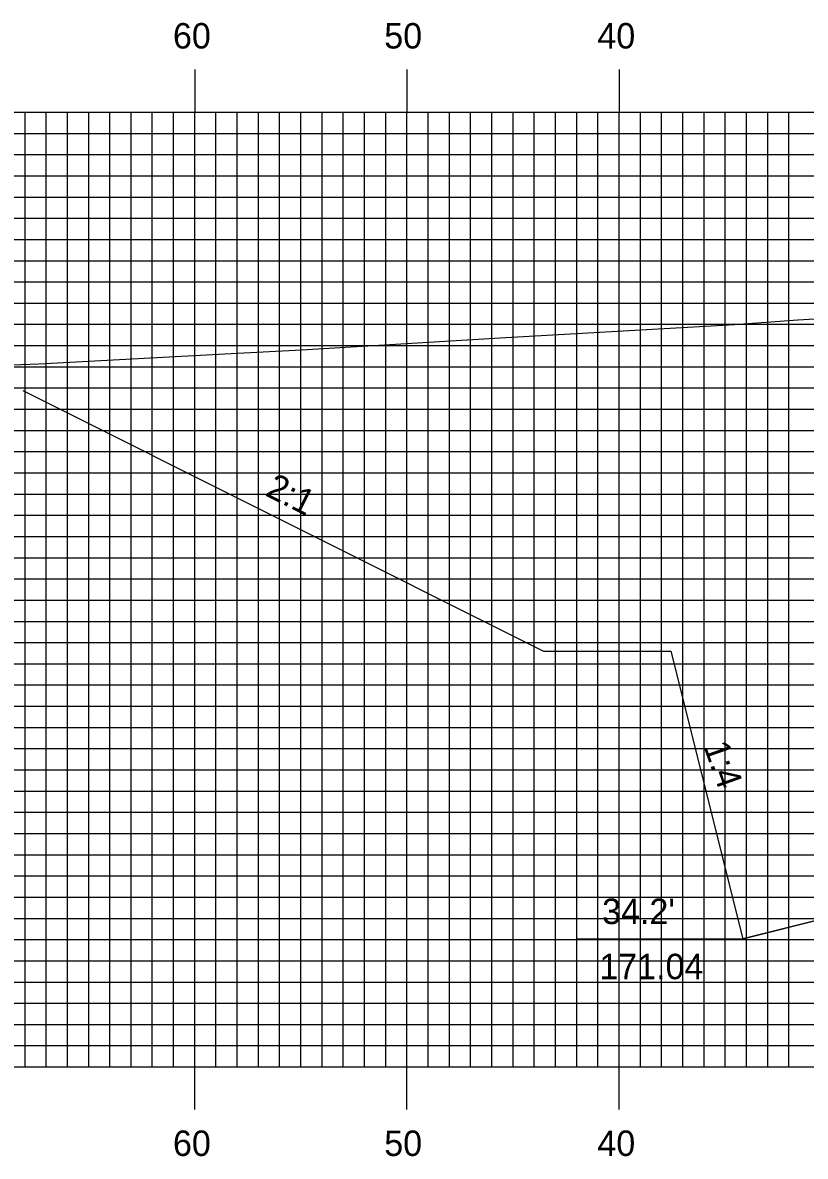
# Model space of a CAD drawing. Extents: x 1795240 to 1795583, y 442591 to 442811.
# Drawn here: x 1795337.3 to 1795374.1, y 442679.4 to 442732.9 of the extents above; entities that cross this region are included whole.
import ezdxf

# ---------------------------------------------------------------- set-up
doc = ezdxf.new("R2010")
doc.units = 0
for name, color, linetype in [('ANNOTATION', 7, 'Continuous'), ('D_Roadway_Centerline', 7, 'Continuous'), ('D_Roadway_SlopeLines', 7, 'Continuous'), ('H_V ANNOTATION', 7, 'Continuous'), ('MAJOR', 7, 'Continuous'), ('MINOR', 7, 'Continuous'), ('PDRAIN', 7, 'Continuous'), ('S_Roadway_Centerline', 7, 'Continuous')]:
    doc.layers.add(name, color=color, linetype=linetype)

msp = doc.modelspace()

# ---------------------------------------------------------------- linework, layer by layer
at = {"layer": 'D_Roadway_Centerline'}
msp.add_lwpolyline([(1795337.256, 442715.538), (1795361.802, 442703.265), (1795367.802, 442703.265), (1795371.192, 442689.704), (1795375.192, 442690.704), (1795385.366, 442693.248), (1795393.366, 442693.568), (1795405.366, 442693.328), (1795417.366, 442693.088), (1795425.366, 442692.768), (1795435.54, 442690.224), (1795439.54, 442689.224), (1795444.366, 442708.528)], dxfattribs=at)
at = {"layer": 'D_Roadway_SlopeLines'}
msp.add_lwpolyline([(1795385.366, 442693.248), (1795371.192, 442689.704)], dxfattribs=at)
at = {"layer": 'MAJOR'}
for p, q in [((1795345.366, 442730.669), (1795345.366, 442728.665)), ((1795355.366, 442730.669), (1795355.366, 442728.665)), ((1795365.366, 442730.669), (1795365.366, 442728.665)), ((1795265.366, 442728.665), (1795545.366, 442728.665)), ((1795265.366, 442728.665), (1795545.366, 442728.665)), ((1795345.366, 442683.665), (1795345.366, 442728.665)), ((1795355.366, 442683.665), (1795355.366, 442728.665)), ((1795365.366, 442683.665), (1795365.366, 442728.665)), ((1795265.366, 442723.665), (1795545.366, 442723.665)), ((1795265.366, 442718.665), (1795545.366, 442718.665)), ((1795265.366, 442713.665), (1795545.366, 442713.665)), ((1795265.366, 442708.665), (1795545.366, 442708.665)), ((1795265.366, 442703.665), (1795545.366, 442703.665)), ((1795265.366, 442698.665), (1795545.366, 442698.665)), ((1795265.366, 442693.665), (1795545.366, 442693.665)), ((1795265.366, 442688.665), (1795545.366, 442688.665)), ((1795265.366, 442683.665), (1795545.366, 442683.665)), ((1795265.366, 442683.665), (1795545.366, 442683.665)), ((1795345.366, 442681.661), (1795345.366, 442683.665)), ((1795355.366, 442681.661), (1795355.366, 442683.665)), ((1795365.366, 442681.661), (1795365.366, 442683.665))]:
    msp.add_line(p, q, dxfattribs=at)
at = {"layer": 'MINOR'}
for p, q in [((1795337.366, 442683.665), (1795337.366, 442728.665)), ((1795338.366, 442683.665), (1795338.366, 442728.665)), ((1795339.366, 442683.665), (1795339.366, 442728.665)), ((1795340.366, 442683.665), (1795340.366, 442728.665)), ((1795341.366, 442683.665), (1795341.366, 442728.665)), ((1795342.366, 442683.665), (1795342.366, 442728.665)), ((1795343.366, 442683.665), (1795343.366, 442728.665)), ((1795344.366, 442683.665), (1795344.366, 442728.665)), ((1795346.366, 442683.665), (1795346.366, 442728.665)), ((1795347.366, 442683.665), (1795347.366, 442728.665)), ((1795348.366, 442683.665), (1795348.366, 442728.665)), ((1795349.366, 442683.665), (1795349.366, 442728.665)), ((1795350.366, 442683.665), (1795350.366, 442728.665)), ((1795351.366, 442683.665), (1795351.366, 442728.665)), ((1795352.366, 442683.665), (1795352.366, 442728.665)), ((1795353.366, 442683.665), (1795353.366, 442728.665)), ((1795354.366, 442683.665), (1795354.366, 442728.665)), ((1795356.366, 442683.665), (1795356.366, 442728.665)), ((1795357.366, 442683.665), (1795357.366, 442728.665)), ((1795358.366, 442683.665), (1795358.366, 442728.665)), ((1795359.366, 442683.665), (1795359.366, 442728.665)), ((1795360.366, 442683.665), (1795360.366, 442728.665)), ((1795361.366, 442683.665), (1795361.366, 442728.665)), ((1795362.366, 442683.665), (1795362.366, 442728.665)), ((1795363.366, 442683.665), (1795363.366, 442728.665)), ((1795364.366, 442683.665), (1795364.366, 442728.665)), ((1795366.366, 442683.665), (1795366.366, 442728.665)), ((1795367.366, 442683.665), (1795367.366, 442728.665)), ((1795368.366, 442683.665), (1795368.366, 442728.665)), ((1795369.366, 442683.665), (1795369.366, 442728.665)), ((1795370.366, 442683.665), (1795370.366, 442728.665)), ((1795371.366, 442683.665), (1795371.366, 442728.665)), ((1795372.366, 442683.665), (1795372.366, 442728.665)), ((1795373.366, 442683.665), (1795373.366, 442728.665)), ((1795265.366, 442727.665), (1795545.366, 442727.665)), ((1795265.366, 442726.665), (1795545.366, 442726.665)), ((1795265.366, 442725.665), (1795545.366, 442725.665)), ((1795265.366, 442724.665), (1795545.366, 442724.665)), ((1795265.366, 442722.665), (1795545.366, 442722.665)), ((1795265.366, 442721.665), (1795545.366, 442721.665)), ((1795265.366, 442720.665), (1795545.366, 442720.665)), ((1795265.366, 442719.665), (1795545.366, 442719.665)), ((1795265.366, 442717.665), (1795545.366, 442717.665)), ((1795265.366, 442716.665), (1795545.366, 442716.665)), ((1795265.366, 442715.665), (1795545.366, 442715.665)), ((1795265.366, 442714.665), (1795545.366, 442714.665)), ((1795265.366, 442712.665), (1795545.366, 442712.665)), ((1795265.366, 442711.665), (1795545.366, 442711.665)), ((1795265.366, 442710.665), (1795545.366, 442710.665)), ((1795265.366, 442709.665), (1795545.366, 442709.665)), ((1795265.366, 442707.665), (1795545.366, 442707.665)), ((1795265.366, 442706.665), (1795545.366, 442706.665)), ((1795265.366, 442705.665), (1795545.366, 442705.665)), ((1795265.366, 442704.665), (1795545.366, 442704.665)), ((1795265.366, 442702.665), (1795545.366, 442702.665)), ((1795265.366, 442701.665), (1795545.366, 442701.665)), ((1795265.366, 442700.665), (1795545.366, 442700.665)), ((1795265.366, 442699.665), (1795545.366, 442699.665)), ((1795265.366, 442697.665), (1795545.366, 442697.665)), ((1795265.366, 442696.665), (1795545.366, 442696.665)), ((1795265.366, 442695.665), (1795545.366, 442695.665)), ((1795265.366, 442694.665), (1795545.366, 442694.665)), ((1795265.366, 442692.665), (1795545.366, 442692.665)), ((1795265.366, 442691.665), (1795545.366, 442691.665)), ((1795265.366, 442690.665), (1795545.366, 442690.665)), ((1795265.366, 442689.665), (1795545.366, 442689.665)), ((1795265.366, 442687.665), (1795545.366, 442687.665)), ((1795265.366, 442686.665), (1795545.366, 442686.665)), ((1795265.366, 442685.665), (1795545.366, 442685.665)), ((1795265.366, 442684.665), (1795545.366, 442684.665))]:
    msp.add_line(p, q, dxfattribs=at)
at = {"layer": 'PDRAIN'}
msp.add_line((1795363.401, 442689.704), (1795371.192, 442689.704), dxfattribs=at)
at = {"layer": 'S_Roadway_Centerline'}
msp.add_lwpolyline([(1795332.201, 442716.579), (1795338.014, 442716.808), (1795347.079, 442717.285), (1795350.391, 442717.459), (1795360.026, 442718.049), (1795370.794, 442718.657), (1795373.791, 442718.875), (1795378.531, 442719.167), (1795390.189, 442719.781), (1795408.969, 442720.094), (1795410.097, 442720.113), (1795410.364, 442720.116), (1795410.815, 442720.127), (1795421.819, 442720.219), (1795441.788, 442720.912), (1795447.801, 442721.165)], dxfattribs=at)

# ---------------------------------------------------------------- texts
at = {"layer": 'ANNOTATION'}
for s, rotation, p in [('2:1', 333.4349, (1795348.637, 442710.617)), ('1:4', 289.484, (1795369.333, 442698.775))]:
    msp.add_text(s, height=1.2, rotation=rotation, dxfattribs=at).set_placement(p)
for s, p in [("34.2'", (1795364.562, 442690.396)), ('171.04', (1795364.429, 442687.796))]:
    msp.add_text(s, height=1.2, dxfattribs=at).set_placement(p)
at = {"layer": 'H_V ANNOTATION'}
for s, p in [('60', (1795344.338, 442731.665)), ('50', (1795354.295, 442731.665)), ('40', (1795364.338, 442731.665)), ('60', (1795344.338, 442679.465)), ('50', (1795354.295, 442679.465)), ('40', (1795364.338, 442679.465))]:
    msp.add_text(s, height=1.2, dxfattribs=at).set_placement(p)

doc.saveas('drawing.dxf')
